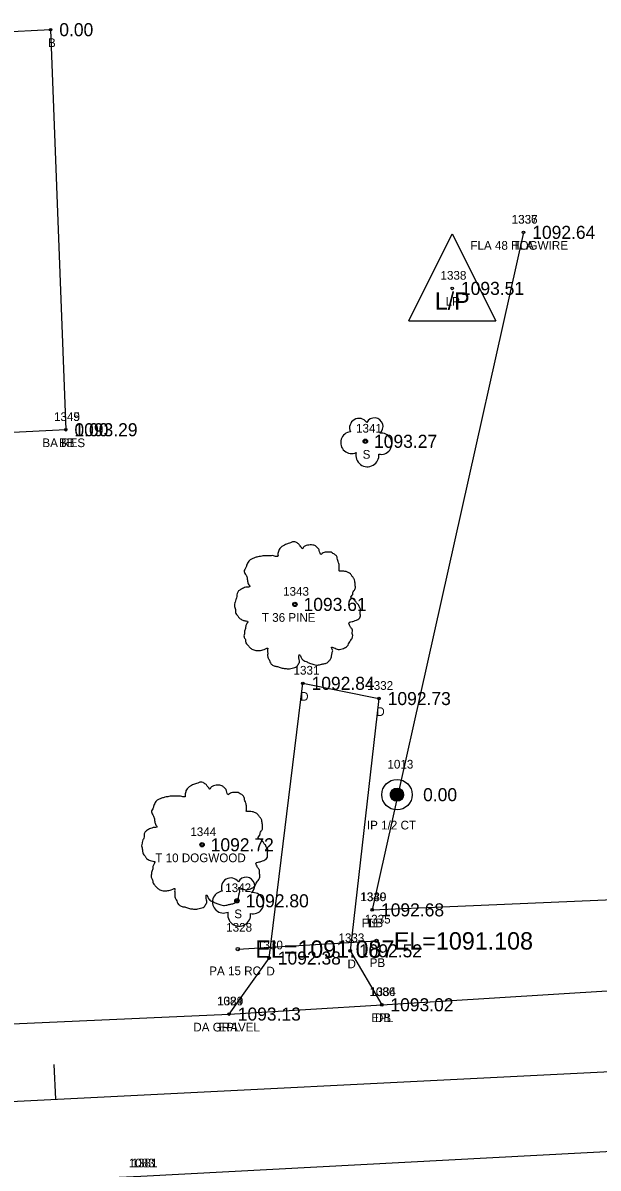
# Model space of a CAD drawing. Extents: x 1539151 to 1541799, y 1198646 to 1201165.
# Drawn here: x 1539789.2 to 1539855.3, y 1199362.5 to 1199494.1 of the extents above; entities that cross this region are included whole.
import ezdxf

# ---------------------------------------------------------------- set-up
doc = ezdxf.new("R2010")
doc.units = 0
for name, color, linetype in [('RD_EX_Bldg', 7, 'Continuous'), ('RD_EX_Bldg_txCode', 7, 'Continuous'), ('RD_EX_DR_Pipe', 7, 'Continuous'), ('RD_EX_DR_Pipe_txCode', 7, 'Continuous'), ('RD_EX_Driveway', 7, 'Continuous'), ('RD_EX_Driveway_txCode', 7, 'Continuous'), ('RD_EX_DV_Prop_txCode', 7, 'Continuous'), ('RD_EX_DV_PropPin', 7, 'Continuous'), ('RD_EX_Fence_Other', 7, 'Continuous'), ('RD_EX_Fence_Other_txCode', 7, 'Continuous'), ('RD_EX_Road', 7, 'Continuous'), ('RD_EX_Road_txCode', 7, 'Continuous'), ('RD_EX_TX_Bldg_ELEV', 7, 'Continuous'), ('RD_EX_TX_Driveway_ELEV', 7, 'Continuous'), ('RD_EX_TX_DV_Prop_ELEV', 7, 'Continuous'), ('RD_EX_TX_Fence_Other_ELEV', 7, 'Continuous'), ('RD_EX_TX_Road_ELEV', 7, 'Continuous'), ('RD_EX_TX_UT_ELEV', 7, 'Continuous'), ('RD_EX_TX_VEG_ELEV', 7, 'Continuous'), ('RD_EX_UT', 7, 'Continuous'), ('RD_EX_UT_txCode', 7, 'Continuous'), ('RD_EX_VEG', 7, 'Continuous'), ('RD_EX_VEG_txCode', 7, 'Continuous'), ('RD_HC_Cl', 7, 'Continuous'), ('RD_HC_Data_Tic', 7, 'Continuous'), ('RD_SMD_Locator', 7, 'Continuous'), ('RD_TX_Pipe_ElevEX', 7, 'Continuous')]:
    doc.layers.add(name, color=color, linetype=linetype)

msp = doc.modelspace()

# ---------------------------------------------------------------- linework, layer by layer
at = {"layer": 'RD_EX_Bldg'}
msp.add_lwpolyline([(1539794.17, 1199447.33), (1539764.43, 1199445.82), (1539762.7, 1199491.82), (1539792.43, 1199493.32), (1539794.17, 1199447.33)], dxfattribs=at)
at = {"layer": 'RD_EX_DR_Pipe'}
msp.add_line((1539813.95, 1199387.63), (1539829.88, 1199388.57), dxfattribs=at)
at = {"layer": 'RD_EX_Driveway'}
msp.add_lwpolyline([(1539812.94, 1199380.16), (1539817.54, 1199386.6), (1539821.42, 1199418.18), (1539830.17, 1199416.43), (1539826.86, 1199387.43), (1539830.48, 1199381.23)], dxfattribs=at)
at = {"layer": 'RD_EX_DV_PropPin'}
for p, q in [((1539831.51, 1199405.19), (1539831.51, 1199405.58)), ((1539831.54, 1199405.08), (1539831.54, 1199405.68)), ((1539831.58, 1199405.01), (1539831.58, 1199405.75)), ((1539831.61, 1199404.96), (1539831.61, 1199405.81)), ((1539831.65, 1199404.91), (1539831.65, 1199405.86)), ((1539831.68, 1199404.87), (1539831.68, 1199405.9)), ((1539831.72, 1199404.83), (1539831.72, 1199405.93)), ((1539831.75, 1199404.8), (1539831.75, 1199405.96)), ((1539831.79, 1199404.77), (1539831.79, 1199405.99)), ((1539831.82, 1199404.75), (1539831.82, 1199406.02)), ((1539831.86, 1199404.73), (1539831.86, 1199406.04)), ((1539831.89, 1199404.71), (1539831.89, 1199406.06)), ((1539831.93, 1199404.69), (1539831.93, 1199406.07)), ((1539831.96, 1199404.67), (1539831.96, 1199406.09)), ((1539832, 1199404.66), (1539832, 1199406.1)), ((1539832.03, 1199404.65), (1539832.03, 1199406.11)), ((1539832.07, 1199404.64), (1539832.07, 1199406.12)), ((1539832.1, 1199404.63), (1539832.1, 1199406.13)), ((1539832.14, 1199404.63), (1539832.14, 1199406.14)), ((1539832.17, 1199404.62), (1539832.17, 1199406.14)), ((1539832.21, 1199404.62), (1539832.21, 1199406.14)), ((1539832.24, 1199404.62), (1539832.24, 1199406.14)), ((1539832.28, 1199404.62), (1539832.28, 1199406.14)), ((1539832.31, 1199404.62), (1539832.31, 1199406.14)), ((1539832.35, 1199404.63), (1539832.35, 1199406.14)), ((1539832.38, 1199404.63), (1539832.38, 1199406.13)), ((1539832.42, 1199404.64), (1539832.42, 1199406.12)), ((1539832.45, 1199404.65), (1539832.45, 1199406.11)), ((1539832.49, 1199404.66), (1539832.49, 1199406.1)), ((1539832.52, 1199404.67), (1539832.52, 1199406.09)), ((1539832.56, 1199404.69), (1539832.56, 1199406.07)), ((1539832.59, 1199404.71), (1539832.59, 1199406.06)), ((1539832.63, 1199404.73), (1539832.63, 1199406.04)), ((1539832.66, 1199404.75), (1539832.66, 1199406.02)), ((1539832.7, 1199404.77), (1539832.7, 1199405.99)), ((1539832.73, 1199404.8), (1539832.73, 1199405.96)), ((1539832.77, 1199404.83), (1539832.77, 1199405.93)), ((1539832.8, 1199404.87), (1539832.8, 1199405.9)), ((1539832.84, 1199404.91), (1539832.84, 1199405.86)), ((1539832.87, 1199404.96), (1539832.87, 1199405.81)), ((1539832.91, 1199405.01), (1539832.91, 1199405.75)), ((1539832.94, 1199405.08), (1539832.94, 1199405.68)), ((1539832.98, 1199405.19), (1539832.98, 1199405.58))]:
    msp.add_line(p, q, dxfattribs=at)
for radius in [1.75, 0.761]:
    msp.add_circle((1539832.24, 1199405.38), radius, dxfattribs=at)
at = {"layer": 'RD_EX_Fence_Other'}
msp.add_line((1539846.78, 1199470.02), (1539829.4, 1199392.14), dxfattribs=at)
at = {"layer": 'RD_EX_Road'}
for points in [[(1539428.76, 1199454.93), (1539416.46, 1199395.23), (1539420.91, 1199377.84), (1539428.29, 1199368.53), (1539440.24, 1199363.06), (1539462.84, 1199364.11), (1539506.12, 1199366.59), (1539554.03, 1199368.02), (1539606.53, 1199370.48), (1539651.89, 1199372.76), (1539672.94, 1199372.91), (1539707.02, 1199374.85), (1539748.7, 1199377.62), (1539769.05, 1199378.19), (1539812.94, 1199380.16), (1539830.48, 1199381.23), (1539857.01, 1199382.87), (1539908.22, 1199385.45), (1539955.82, 1199389.74), (1539996.13, 1199397.4), (1540037.85, 1199410.51), (1540050.26, 1199415.61), (1540093.12, 1199444.78)], [(1539376.14, 1199238.5), (1539389.65, 1199292.82), (1539395.62, 1199315.5), (1539405.98, 1199330.34), (1539420.48, 1199338.44), (1539434.13, 1199341.92), (1539458.27, 1199343.35), (1539505.21, 1199345.92), (1539518.44, 1199346.66), (1539558.02, 1199348.62), (1539607.46, 1199351.19), (1539654.3, 1199353.64), (1539676.57, 1199355), (1539708.42, 1199356.93), (1539757.47, 1199359.08), (1539779.44, 1199360.44), (1539802.8, 1199361.54), (1539858.43, 1199364.46), (1539908.44, 1199366.95), (1539925.86, 1199367.85), (1539963.35, 1199372.53)]]:
    msp.add_lwpolyline(points, dxfattribs=at)
at = {"layer": 'RD_EX_UT'}
for p, q in [((1539833.59, 1199459.85), (1539838.59, 1199469.85)), ((1539838.59, 1199469.85), (1539843.59, 1199459.85)), ((1539833.59, 1199459.85), (1539843.59, 1199459.85))]:
    msp.add_line(p, q, dxfattribs=at)
at = {"layer": 'RD_EX_VEG'}
msp.add_lwpolyline([(1539846.78, 1199470.02), (1539829.4, 1199392.14), (1539911.66, 1199395.68), (1539954.64, 1199401.74), (1539995.07, 1199408.66), (1539952.34, 1199425.54), (1539926.15, 1199439.35), (1539942.46, 1199485.66)], dxfattribs=at)
for centre, radius in [((1539828.6, 1199446), 0.25), ((1539820.5, 1199427.25), 0.25), ((1539820.48, 1199427.23), 0.0001), ((1539809.83, 1199399.62), 0.25), ((1539809.82, 1199399.61), 0.0001), ((1539813.85, 1199393.18), 0.25)]:
    msp.add_circle(centre, radius, dxfattribs=at)
for centre, radius, start, end in [((1539827.87, 1199447.55), 1.08, 34.9763, 204.756), ((1539829.64, 1199447.7), 0.995, 308.7626, 152.0467), ((1539827.03, 1199445.85), 1.26, 96.4518, 294.734), ((1539830.43, 1199445.72), 1.22, 256.5667, 98.1046), ((1539828.84, 1199444.4), 1.32, 166.8827, 5.7589), ((1539813.13, 1199394.73), 1.08, 34.9763, 204.756), ((1539814.89, 1199394.89), 0.995, 308.7626, 152.0467), ((1539812.29, 1199393.03), 1.26, 96.4518, 294.734), ((1539815.69, 1199392.9), 1.22, 256.5667, 98.1046), ((1539814.1, 1199391.59), 1.32, 166.8827, 5.7589)]:
    msp.add_arc(centre, radius, start, end, dxfattribs=at)
for points in [[(1539820.63, 1199434.42), (1539820.33, 1199434.44), (1539820, 1199434.34), (1539819.75, 1199434.24), (1539819.53, 1199434.17), (1539819.3, 1199434.07), (1539819, 1199433.89), (1539818.78, 1199433.69), (1539818.65, 1199433.44), (1539818.6, 1199433.22), (1539818.55, 1199432.95), (1539818.55, 1199432.77), (1539818.43, 1199432.75), (1539818.28, 1199432.77), (1539818.03, 1199432.85), (1539817.78, 1199432.85), (1539817.53, 1199432.85), (1539817.18, 1199432.82), (1539816.83, 1199432.82), (1539816.56, 1199432.77), (1539816.23, 1199432.72), (1539815.86, 1199432.6), (1539815.51, 1199432.47), (1539815.21, 1199432.22), (1539814.96, 1199431.75), (1539814.83, 1199431.4), (1539814.68, 1199431.15), (1539814.83, 1199430.7), (1539815.01, 1199430.35), (1539815.03, 1199430.15), (1539815.11, 1199429.72), (1539815.21, 1199429.5), (1539815.33, 1199429.3), (1539815.26, 1199429.27), (1539814.88, 1199429.22), (1539814.58, 1199429.12), (1539814.16, 1199428.9), (1539813.93, 1199428.67), (1539813.83, 1199428.35), (1539813.81, 1199428), (1539813.71, 1199427.8), (1539813.63, 1199427.52), (1539813.61, 1199427.45), (1539813.56, 1199427.12), (1539813.66, 1199426.67), (1539813.68, 1199426.32), (1539813.81, 1199426.1), (1539813.96, 1199425.92), (1539814.13, 1199425.67), (1539814.53, 1199425.45), (1539814.86, 1199425.35), (1539815.06, 1199425.32), (1539814.88, 1199424.82), (1539814.83, 1199424.47), (1539814.71, 1199424.07), (1539814.71, 1199424), (1539814.66, 1199423.52), (1539814.81, 1199423.2), (1539814.88, 1199422.82), (1539815.06, 1199422.6), (1539815.33, 1199422.3), (1539815.66, 1199422.07), (1539816.16, 1199421.95), (1539816.56, 1199421.97), (1539817.13, 1199422.15), (1539817.38, 1199422.22), (1539817.36, 1199422.05), (1539817.38, 1199421.67), (1539817.38, 1199421.25), (1539817.53, 1199420.93), (1539817.63, 1199420.65), (1539817.78, 1199420.4), (1539818.11, 1199420.18), (1539818.5, 1199420.1), (1539818.93, 1199419.95), (1539819.38, 1199419.88), (1539819.88, 1199419.85), (1539820.48, 1199420), (1539820.75, 1199420.13), (1539820.85, 1199420.3), (1539821.05, 1199420.68), (1539821, 1199420.9), (1539821.03, 1199421.5), (1539821.13, 1199421.33), (1539821.3, 1199420.98), (1539821.8, 1199420.68), (1539822.2, 1199420.5), (1539822.68, 1199420.35), (1539822.98, 1199420.28), (1539823.45, 1199420.35), (1539823.83, 1199420.43), (1539824.2, 1199420.55), (1539824.5, 1199420.83), (1539824.68, 1199421.1), (1539824.73, 1199421.38), (1539824.8, 1199421.75), (1539824.85, 1199421.92)], [(1539824.85, 1199421.92), (1539824.78, 1199422.1), (1539824.73, 1199422.35), (1539824.8, 1199422.32), (1539824.98, 1199422.27), (1539825.25, 1199422.15), (1539825.48, 1199422.07), (1539825.8, 1199422.1), (1539826.08, 1199422.2), (1539826.53, 1199422.47), (1539826.8, 1199422.95), (1539827.08, 1199423.35), (1539827.15, 1199423.67), (1539827.1, 1199423.9), (1539827.08, 1199424.4), (1539826.88, 1199424.65), (1539826.83, 1199424.77), (1539826.73, 1199425.17), (1539826.8, 1199425.22), (1539827.08, 1199425.27), (1539827.45, 1199425.4), (1539827.73, 1199425.52), (1539827.95, 1199425.7), (1539828.03, 1199425.92), (1539828, 1199426.32), (1539828.05, 1199426.72), (1539827.98, 1199426.87), (1539827.88, 1199427.02), (1539827.8, 1199427.22), (1539827.65, 1199427.37), (1539827.55, 1199427.52), (1539827.45, 1199427.62), (1539827.33, 1199427.77), (1539827.15, 1199427.9), (1539827, 1199427.95), (1539826.95, 1199428.1), (1539827.1, 1199428.3), (1539827.15, 1199428.4), (1539827.18, 1199428.62), (1539827.4, 1199428.97), (1539827.45, 1199429.37), (1539827.4, 1199429.8), (1539827.35, 1199430.07), (1539827.2, 1199430.35), (1539827, 1199430.6), (1539826.88, 1199430.77), (1539826.7, 1199430.9), (1539826.38, 1199431.02), (1539826.13, 1199431.07), (1539825.78, 1199431.07), (1539825.58, 1199431.12), (1539825.6, 1199431.17), (1539825.6, 1199431.32), (1539825.6, 1199431.6), (1539825.53, 1199432.05), (1539825.38, 1199432.55), (1539825.38, 1199432.57), (1539825.28, 1199432.82), (1539825.05, 1199433.02), (1539824.88, 1199433.12), (1539824.68, 1199433.24), (1539824.43, 1199433.27), (1539824.13, 1199433.27), (1539823.85, 1199433.22), (1539823.65, 1199433.12), (1539823.48, 1199432.99), (1539823.4, 1199433.14), (1539823.3, 1199433.44), (1539823.25, 1199433.59), (1539823.1, 1199433.77), (1539822.88, 1199433.97), (1539822.43, 1199434.09), (1539821.8, 1199434.02), (1539821.5, 1199433.82), (1539821.35, 1199433.64), (1539821.3, 1199433.77), (1539821.1, 1199433.97), (1539821, 1199434.14), (1539820.83, 1199434.27), (1539820.68, 1199434.37), (1539820.58, 1199434.42)], [(1539809.97, 1199406.79), (1539809.67, 1199406.82), (1539809.34, 1199406.72), (1539809.09, 1199406.62), (1539808.87, 1199406.54), (1539808.64, 1199406.44), (1539808.34, 1199406.27), (1539808.12, 1199406.07), (1539807.99, 1199405.82), (1539807.94, 1199405.59), (1539807.89, 1199405.32), (1539807.89, 1199405.14), (1539807.77, 1199405.12), (1539807.62, 1199405.14), (1539807.37, 1199405.22), (1539807.12, 1199405.22), (1539806.87, 1199405.22), (1539806.52, 1199405.19), (1539806.17, 1199405.19), (1539805.89, 1199405.14), (1539805.57, 1199405.09), (1539805.19, 1199404.97), (1539804.84, 1199404.84), (1539804.54, 1199404.59), (1539804.29, 1199404.12), (1539804.17, 1199403.77), (1539804.02, 1199403.52), (1539804.17, 1199403.07), (1539804.34, 1199402.72), (1539804.37, 1199402.52), (1539804.44, 1199402.09), (1539804.54, 1199401.87), (1539804.67, 1199401.67), (1539804.59, 1199401.64), (1539804.22, 1199401.59), (1539803.92, 1199401.49), (1539803.49, 1199401.27), (1539803.27, 1199401.04), (1539803.17, 1199400.72), (1539803.14, 1199400.37), (1539803.04, 1199400.17), (1539802.97, 1199399.89), (1539802.94, 1199399.82), (1539802.89, 1199399.5), (1539802.99, 1199399.05), (1539803.02, 1199398.7), (1539803.14, 1199398.47), (1539803.29, 1199398.3), (1539803.47, 1199398.05), (1539803.87, 1199397.82), (1539804.19, 1199397.72), (1539804.39, 1199397.7), (1539804.22, 1199397.2), (1539804.17, 1199396.85), (1539804.04, 1199396.45), (1539804.04, 1199396.37), (1539803.99, 1199395.9), (1539804.14, 1199395.57), (1539804.22, 1199395.2), (1539804.39, 1199394.97), (1539804.67, 1199394.67), (1539804.99, 1199394.45), (1539805.49, 1199394.32), (1539805.89, 1199394.35), (1539806.47, 1199394.52), (1539806.72, 1199394.6), (1539806.69, 1199394.42), (1539806.72, 1199394.05), (1539806.72, 1199393.62), (1539806.87, 1199393.3), (1539806.97, 1199393.02), (1539807.12, 1199392.77), (1539807.44, 1199392.55), (1539807.84, 1199392.47), (1539808.27, 1199392.32), (1539808.72, 1199392.25), (1539809.22, 1199392.22), (1539809.82, 1199392.37), (1539810.09, 1199392.5), (1539810.19, 1199392.67), (1539810.39, 1199393.05), (1539810.34, 1199393.27), (1539810.37, 1199393.87), (1539810.47, 1199393.7), (1539810.64, 1199393.35), (1539811.14, 1199393.05), (1539811.54, 1199392.87), (1539812.01, 1199392.72), (1539812.31, 1199392.65), (1539812.79, 1199392.72), (1539813.16, 1199392.8), (1539813.54, 1199392.92), (1539813.84, 1199393.2), (1539814.01, 1199393.47), (1539814.06, 1199393.75), (1539814.14, 1199394.12), (1539814.19, 1199394.3)], [(1539814.19, 1199394.3), (1539814.11, 1199394.47), (1539814.06, 1199394.72), (1539814.14, 1199394.7), (1539814.31, 1199394.65), (1539814.59, 1199394.52), (1539814.81, 1199394.45), (1539815.14, 1199394.47), (1539815.41, 1199394.57), (1539815.86, 1199394.85), (1539816.14, 1199395.32), (1539816.41, 1199395.72), (1539816.49, 1199396.05), (1539816.44, 1199396.27), (1539816.41, 1199396.77), (1539816.21, 1199397.02), (1539816.16, 1199397.15), (1539816.06, 1199397.55), (1539816.14, 1199397.6), (1539816.41, 1199397.65), (1539816.79, 1199397.77), (1539817.06, 1199397.9), (1539817.29, 1199398.07), (1539817.36, 1199398.3), (1539817.34, 1199398.7), (1539817.39, 1199399.1), (1539817.31, 1199399.25), (1539817.21, 1199399.4), (1539817.14, 1199399.6), (1539816.99, 1199399.74), (1539816.89, 1199399.89), (1539816.79, 1199399.99), (1539816.66, 1199400.14), (1539816.49, 1199400.27), (1539816.34, 1199400.32), (1539816.29, 1199400.47), (1539816.44, 1199400.67), (1539816.49, 1199400.77), (1539816.51, 1199400.99), (1539816.74, 1199401.34), (1539816.79, 1199401.74), (1539816.74, 1199402.17), (1539816.69, 1199402.44), (1539816.54, 1199402.72), (1539816.34, 1199402.97), (1539816.21, 1199403.14), (1539816.04, 1199403.27), (1539815.71, 1199403.39), (1539815.46, 1199403.44), (1539815.11, 1199403.44), (1539814.91, 1199403.49), (1539814.94, 1199403.54), (1539814.94, 1199403.69), (1539814.94, 1199403.97), (1539814.86, 1199404.42), (1539814.71, 1199404.92), (1539814.71, 1199404.94), (1539814.61, 1199405.19), (1539814.39, 1199405.39), (1539814.21, 1199405.49), (1539814.01, 1199405.62), (1539813.76, 1199405.64), (1539813.46, 1199405.64), (1539813.19, 1199405.59), (1539812.99, 1199405.49), (1539812.81, 1199405.37), (1539812.74, 1199405.52), (1539812.64, 1199405.82), (1539812.59, 1199405.97), (1539812.44, 1199406.14), (1539812.21, 1199406.34), (1539811.76, 1199406.47), (1539811.14, 1199406.39), (1539810.84, 1199406.19), (1539810.69, 1199406.02), (1539810.64, 1199406.14), (1539810.44, 1199406.34), (1539810.34, 1199406.52), (1539810.17, 1199406.64), (1539810.02, 1199406.74), (1539809.92, 1199406.79)]]:
    msp.add_spline(points, degree=3, dxfattribs=at)
at = {"layer": 'RD_HC_Cl'}
msp.add_line((1539393.53, 1199350.4), (1539900.86, 1199375.77), dxfattribs=at)
at = {"layer": 'RD_HC_Data_Tic'}
msp.add_line((1539793.03, 1199370.38), (1539792.83, 1199374.37), dxfattribs=at)
at = {"layer": 'RD_SMD_Locator'}
for centre, radius in [((1539792.43, 1199493.32), 0.15), ((1539846.78, 1199470.02), 0.15), ((1539846.78, 1199470.02), 0.15), ((1539838.59, 1199463.58), 0.15), ((1539794.17, 1199447.33), 0.15), ((1539794.17, 1199447.33), 0.15), ((1539828.6, 1199446), 0.15), ((1539820.5, 1199427.25), 0.15), ((1539821.42, 1199418.18), 0.15), ((1539830.17, 1199416.43), 0.15), ((1539832.24, 1199405.38), 0.15), ((1539809.83, 1199399.62), 0.15), ((1539813.85, 1199393.18), 0.15), ((1539829.4, 1199392.14), 0.15), ((1539829.4, 1199392.14), 0.15), ((1539829.88, 1199388.57), 0.2), ((1539813.95, 1199387.63), 0.2), ((1539817.54, 1199386.6), 0.15), ((1539826.86, 1199387.43), 0.15), ((1539812.94, 1199380.16), 0.15), ((1539812.94, 1199380.16), 0.15), ((1539830.48, 1199381.23), 0.15), ((1539830.48, 1199381.23), 0.15)]:
    msp.add_circle(centre, radius, dxfattribs=at)

# ---------------------------------------------------------------- texts
at = {"layer": 'RD_EX_Bldg_txCode'}
for s, p in [('B', (1539792.13, 1199491.32)), ('1345', (1539792.82, 1199448.33)), ('1349', (1539792.82, 1199448.33)), ('BA RES', (1539791.49, 1199445.33)), ('BB', (1539793.39, 1199445.33))]:
    msp.add_text(s, height=1, dxfattribs=at).set_placement(p)
at = {"layer": 'RD_EX_DR_Pipe_txCode'}
for s, p in [('1335', (1539828.53, 1199390.57)), ('1328', (1539812.61, 1199389.63)), ('PA 15 RC', (1539810.66, 1199384.63)), ('PB', (1539829.1, 1199385.57))]:
    msp.add_text(s, height=1, dxfattribs=at).set_placement(p)
at = {"layer": 'RD_EX_Driveway_txCode'}
for s, p in [('1331', (1539820.35, 1199419.18)), ('1332', (1539828.82, 1199417.43)), ('D', (1539821.11, 1199416.18)), ('D', (1539829.86, 1199414.43)), ('1333', (1539825.51, 1199388.43)), ('1330', (1539816.15, 1199387.6)), ('D', (1539817.23, 1199384.6)), ('D', (1539826.55, 1199385.43)), ('1334', (1539829.14, 1199382.23)), ('1329', (1539811.59, 1199381.16)), ('DB', (1539829.7, 1199379.23)), ('DA GRAVEL', (1539808.83, 1199378.16)), ('1381', (1539801.74, 1199362.54))]:
    msp.add_text(s, height=1, dxfattribs=at).set_placement(p)
at = {"layer": 'RD_EX_DV_Prop_txCode'}
for s, p in [('1013', (1539831.14, 1199408.38)), ('IP 1/2 CT', (1539828.78, 1199401.38))]:
    msp.add_text(s, height=1, dxfattribs=at).set_placement(p)
at = {"layer": 'RD_EX_Fence_Other_txCode'}
for s, p in [('1336', (1539845.41, 1199471.02)), ('FLA 48 HOGWIRE', (1539840.67, 1199468.02)), ('1339', (1539828.05, 1199393.14)), ('FLB', (1539828.19, 1199390.14))]:
    msp.add_text(s, height=1, dxfattribs=at).set_placement(p)
at = {"layer": 'RD_EX_Road_txCode'}
for s, p in [('1086', (1539829.07, 1199382.23)), ('1084', (1539811.55, 1199381.16)), ('EPL', (1539829.28, 1199379.23)), ('EPL', (1539811.73, 1199378.16)), ('1083', (1539801.41, 1199362.54))]:
    msp.add_text(s, height=1, dxfattribs=at).set_placement(p)
at = {"layer": 'RD_EX_TX_Bldg_ELEV'}
for s, p in [('0.00', (1539793.43, 1199492.57)), ('0.00', (1539795.17, 1199446.58)), ('1093.29', (1539795.17, 1199446.58))]:
    msp.add_text(s, height=1.5, dxfattribs=at).set_placement(p)
at = {"layer": 'RD_EX_TX_Driveway_ELEV'}
for s, p in [('1092.84', (1539822.42, 1199417.43)), ('1092.73', (1539831.17, 1199415.68)), ('1092.52', (1539827.86, 1199386.68)), ('1092.38', (1539818.54, 1199385.85)), ('1093.02', (1539831.48, 1199380.48)), ('1093.13', (1539813.94, 1199379.41))]:
    msp.add_text(s, height=1.5, dxfattribs=at).set_placement(p)
at = {"layer": 'RD_EX_TX_DV_Prop_ELEV'}
msp.add_text('0.00', height=1.5, dxfattribs=at).set_placement((1539835.24, 1199404.63))
at = {"layer": 'RD_EX_TX_Fence_Other_ELEV'}
for s, p in [('1092.64', (1539847.78, 1199469.27)), ('1092.68', (1539830.4, 1199391.39))]:
    msp.add_text(s, height=1.5, dxfattribs=at).set_placement(p)
at = {"layer": 'RD_EX_TX_Road_ELEV'}
for s, p in [('1093.02', (1539831.48, 1199380.48)), ('1093.13', (1539813.94, 1199379.41))]:
    msp.add_text(s, height=1.5, dxfattribs=at).set_placement(p)
at = {"layer": 'RD_EX_TX_UT_ELEV'}
msp.add_text('1093.51', height=1.5, dxfattribs=at).set_placement((1539839.59, 1199462.83))
at = {"layer": 'RD_EX_TX_VEG_ELEV'}
for s, p in [('1092.64', (1539847.78, 1199469.27)), ('1093.27', (1539829.6, 1199445.25)), ('1093.61', (1539821.5, 1199426.5)), ('1092.72', (1539810.83, 1199398.87)), ('1092.80', (1539814.85, 1199392.43)), ('1092.68', (1539830.4, 1199391.39))]:
    msp.add_text(s, height=1.5, dxfattribs=at).set_placement(p)
at = {"layer": 'RD_EX_UT'}
msp.add_text('L/P', height=2, dxfattribs=at).set_placement((1539836.58, 1199461.13))
at = {"layer": 'RD_EX_UT_txCode'}
for s, p in [('1338', (1539837.24, 1199464.58)), ('LP', (1539837.83, 1199461.58))]:
    msp.add_text(s, height=1, dxfattribs=at).set_placement(p)
at = {"layer": 'RD_EX_VEG_txCode'}
for s, p in [('1337', (1539845.43, 1199471.02)), ('TLA', (1539845.52, 1199468.02)), ('1341', (1539827.53, 1199447)), ('S', (1539828.29, 1199444)), ('1343', (1539819.15, 1199428.25)), ('T 36 PINE', (1539816.71, 1199425.25)), ('1344', (1539808.49, 1199400.62)), ('T 10 DOGWOOD', (1539804.46, 1199397.62)), ('1342', (1539812.5, 1199394.18)), ('1340', (1539828.01, 1199393.14)), ('S', (1539813.54, 1199391.18)), ('TL', (1539828.62, 1199390.14))]:
    msp.add_text(s, height=1, dxfattribs=at).set_placement(p)
at = {"layer": 'RD_TX_Pipe_ElevEX'}
for s, p in [('EL=1091.108', (1539831.88, 1199387.57)), ('EL=1091.087', (1539815.95, 1199386.63))]:
    msp.add_text(s, height=2, dxfattribs=at).set_placement(p)

doc.saveas('drawing.dxf')
